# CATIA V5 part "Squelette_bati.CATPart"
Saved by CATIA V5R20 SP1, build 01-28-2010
Part number: Squelette_bati
Publications: "largeur_chevalet", "Longueur_bati", "Hauteur_pontet", "decalage_pontet", "decalage_axe", "Largeur_vibrato", "Hauteur_vibrato", "Droite.2", "Plan.9", "Plan.5", "Plan.1", "Plan.2", "Plan.3", "Plan.4", "Plan.6", "Plan.7", "Plan.8", "Point.1", "Droite.1", "Point.2"
Bounding box of the stored display mesh (mm): x -30 to 30, y 1 to 20, z 35 to 45
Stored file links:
  F:\Pro\Emplois\1_Chercheur\ThinkMOTION\MMS\MMS_GR1\abruchon\Catia\Squelette_bati.CATPart
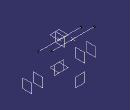
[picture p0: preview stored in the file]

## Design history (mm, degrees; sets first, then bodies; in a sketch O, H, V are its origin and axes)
Parameters
  largeur_chevalet = 60 mm
  Longueur_bati = 30 mm
  Hauteur_pontet = 45 mm
  decalage_pontet = 10 mm
  decalage_axe = 5 mm
  Largeur_vibrato = 90 mm
  Hauteur_vibrato = 40 mm
Set1 "Set_bati"
  Plane1: type Offset, RefPlane xy-plane, Offset 0
  Plane2: type Offset, RefPlane Plane1, Offset 40 {= Hauteur_vibrato}
  Plane3: type Offset, RefPlane zx-plane, Offset 0
  Plane4: type Offset, RefPlane Plane3, Offset 30 {= Longueur_bati}
  Plane5: type Offset, RefPlane yz-plane, Offset 30 {= largeur_chevalet /2}
  Plane6: type Offset, RefPlane yz-plane, Offset 30 {= largeur_chevalet /2}, reversed
  Plane7: type Offset, RefPlane yz-plane, Offset 45 {= Largeur_vibrato /2}
  Plane8: type Offset, RefPlane yz-plane, Offset 45 {= Largeur_vibrato /2}, reversed
  Point1: (0, 20 {= Longueur_bati -decalage_pontet}, 45 {= Hauteur_pontet})
  Line1: type PtDir, RefPoint Point1, Direction Plane7, Start -30, End 30 {= largeur_chevalet /2}
  Point2: (0, 1, 35 {= Hauteur_vibrato -decalage_axe})
  Line2: type PtDir, RefPoint Point2, Direction Plane5, Start -30, End 30
  Plane9: type Normal, Curve Line2
Body1 (main body)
